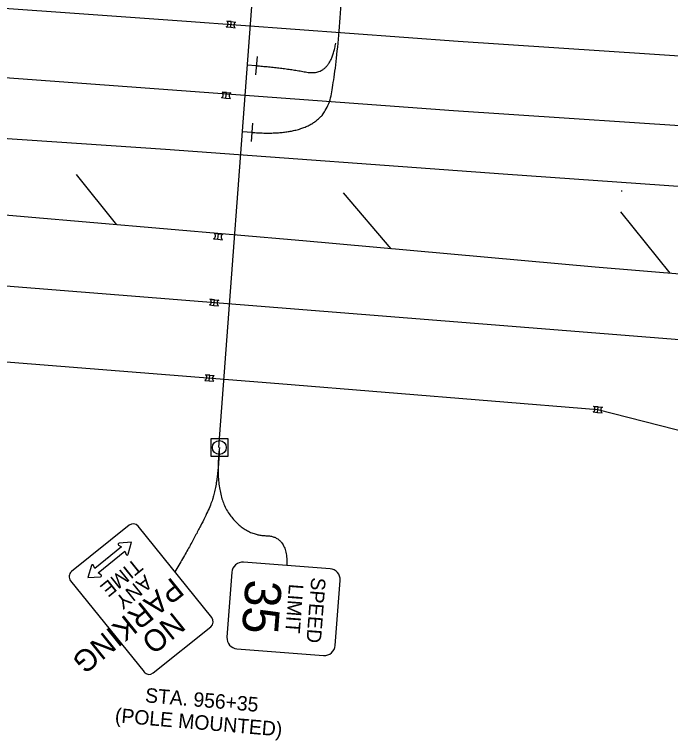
# Model space of a CAD drawing. Extents: x 1847379 to 1850904, y 217032 to 220169.
# Drawn here: x 1849731.4 to 1849844.7, y 218693.6 to 218819 of the extents above; entities that cross this region are included whole.
import ezdxf

# ---------------------------------------------------------------- set-up
doc = ezdxf.new("R2010")
doc.units = 0
for name, color, linetype in [('PM_P_Cells', 7, 'Continuous'), ('PM_P_CL_Double_Solid', 7, 'Continuous'), ('PM_P_Edge_Line', 7, 'Continuous'), ('PM_P_Lane_Line', 7, 'Continuous'), ('PM_P_Transverse_Line', 7, 'Continuous'), ('SG_X_Poles', 7, 'Continuous'), ('SN_X_Public', 7, 'Continuous'), ('SN_X_Text', 7, 'Continuous')]:
    doc.layers.add(name, color=color, linetype=linetype)

msp = doc.modelspace()

# ---------------------------------------------------------------- linework, layer by layer
at = {"layer": 'PM_P_Cells'}
for p, q in [((1849768.83, 218817.79), (1849768.06, 218817.86)), ((1849768.06, 218817.86), (1849768.83, 218817.79)), ((1849768.74, 218816.81), (1849768.83, 218817.79)), ((1849768.83, 218817.79), (1849769.59, 218817.72)), ((1849767.97, 218816.88), (1849768.74, 218816.81)), ((1849767.97, 218816.88), (1849768.74, 218816.81)), ((1849768.74, 218816.81), (1849769.51, 218816.74)), ((1849768.01, 218805.56), (1849767.24, 218805.63)), ((1849767.24, 218805.63), (1849768.01, 218805.56)), ((1849767.92, 218804.59), (1849768.01, 218805.56)), ((1849768.01, 218805.56), (1849768.78, 218805.49)), ((1849767.15, 218804.66), (1849767.92, 218804.59)), ((1849767.15, 218804.66), (1849767.92, 218804.59)), ((1849767.92, 218804.59), (1849768.69, 218804.52)), ((1849765.77, 218780.25), (1849766.54, 218780.18)), ((1849765.77, 218780.25), (1849766.54, 218780.18)), ((1849766.63, 218781.15), (1849765.86, 218781.22)), ((1849765.86, 218781.22), (1849766.63, 218781.15)), ((1849766.54, 218780.18), (1849766.63, 218781.15)), ((1849766.54, 218780.18), (1849767.31, 218780.11)), ((1849766.63, 218781.15), (1849767.4, 218781.08)), ((1849765.08, 218768.84), (1849765.84, 218768.77)), ((1849765.08, 218768.84), (1849765.84, 218768.77)), ((1849765.93, 218769.75), (1849765.16, 218769.82)), ((1849765.16, 218769.82), (1849765.93, 218769.75)), ((1849765.84, 218768.77), (1849765.93, 218769.75)), ((1849765.84, 218768.77), (1849766.61, 218768.7)), ((1849765.93, 218769.75), (1849766.7, 218769.68)), ((1849765.13, 218756.72), (1849764.36, 218756.78)), ((1849764.36, 218756.78), (1849765.13, 218756.72)), ((1849765.04, 218755.74), (1849765.13, 218756.72)), ((1849765.13, 218756.72), (1849765.9, 218756.65)), ((1849764.28, 218755.81), (1849765.04, 218755.74)), ((1849764.28, 218755.81), (1849765.04, 218755.74)), ((1849765.04, 218755.74), (1849765.81, 218755.67)), ((1849832.21, 218751.25), (1849831.44, 218751.32)), ((1849831.44, 218751.32), (1849832.21, 218751.25)), ((1849832.12, 218750.28), (1849832.21, 218751.25)), ((1849832.21, 218751.25), (1849832.98, 218751.18)), ((1849831.35, 218750.35), (1849832.12, 218750.28)), ((1849831.35, 218750.35), (1849832.12, 218750.28)), ((1849832.12, 218750.28), (1849832.89, 218750.21))]:
    msp.add_line(p, q, dxfattribs=at)
for centre, start, end in [((1849767.71, 218817.4), 296.8063, 52.8586), ((1849767.71, 218817.4), 296.8063, 52.8586), ((1849769.85, 218817.2), 116.8063, 232.8586), ((1849766.89, 218805.17), 296.8063, 52.8586), ((1849766.89, 218805.17), 296.8063, 52.8586), ((1849769.04, 218804.98), 116.8063, 232.8586), ((1849765.52, 218780.76), 296.8063, 52.8586), ((1849765.52, 218780.76), 296.8063, 52.8586), ((1849767.66, 218780.57), 116.8063, 232.8586), ((1849764.82, 218769.36), 296.8063, 52.8586), ((1849764.82, 218769.36), 296.8063, 52.8586), ((1849766.96, 218769.16), 116.8063, 232.8586), ((1849764.02, 218756.33), 296.8063, 52.8586), ((1849764.02, 218756.33), 296.8063, 52.8586), ((1849766.16, 218756.13), 116.8063, 232.8586), ((1849831.09, 218750.86), 296.8063, 52.8586), ((1849831.09, 218750.86), 296.8063, 52.8586), ((1849833.24, 218750.67), 116.8063, 232.8586)]:
    msp.add_arc(centre, 0.576, start, end, dxfattribs=at)
at = {"layer": 'PM_P_CL_Double_Solid'}
for p, q in [((1849733.07, 218784.06), (1849683.32, 218788.47)), ((1849781.21, 218779.91), (1849733.07, 218784.06)), ((1849831.69, 218775.35), (1849781.21, 218779.91)), ((1849882.04, 218771.28), (1849831.69, 218775.35))]:
    msp.add_line(p, q, dxfattribs=at)
at = {"layer": 'PM_P_Edge_Line'}
for p, q in [((1849705.27, 218799.28), (1849757.46, 218795.73)), ((1849757.46, 218795.73), (1849815.8, 218791.52)), ((1849815.8, 218791.52), (1849863.14, 218788.13))]:
    msp.add_line(p, q, dxfattribs=at)
for points in [[(1849624.07, 218766.93), (1849675.44, 218763.35), (1849725.59, 218759.36), (1849777.06, 218755.28), (1849832.17, 218750.77)], [(1849832.17, 218750.77), (1849894.17, 218734.94), (1849941.43, 218730.63), (1849992.34, 218726.14), (1850039.4, 218721.8), (1850086.44, 218717.54), (1850135.69, 218713.18), (1850171.07, 218709.94)]]:
    msp.add_lwpolyline(points, dxfattribs=at)
at = {"layer": 'PM_P_Lane_Line'}
msp.add_line((1849606.07, 218781.96), (1849881.96, 218760.04), dxfattribs=at)
for points in [[(1849608.99, 218828.81), (1849660.31, 218825.18), (1849710.18, 218821.58), (1849761.09, 218817.87), (1849808.06, 218814.41), (1849858.45, 218811.1), (1849907.69, 218807.67), (1849958.4, 218803.79), (1850015.55, 218799.15), (1850068.16, 218794.66), (1850119.07, 218790.16), (1850168.5, 218785.91), (1850217.76, 218781.65), (1850267.02, 218777.03), (1850317.3, 218772.15), (1850366.38, 218767.35), (1850416.59, 218762.59), (1850466.65, 218757.55), (1850517.86, 218752.55), (1850566.57, 218747.88), (1850616.29, 218742.91), (1850664.9, 218737.75)], [(1849608.14, 218816.84), (1849659.46, 218813.21), (1849709.31, 218809.62), (1849760.21, 218805.9), (1849807.22, 218802.44), (1849857.63, 218799.12), (1849906.82, 218795.7), (1849957.46, 218791.82), (1850014.55, 218787.19), (1850067.13, 218782.71), (1850118.03, 218778.2), (1850167.47, 218773.95), (1850186.14, 218772.34)]]:
    msp.add_lwpolyline(points, dxfattribs=at)
at = {"layer": 'PM_P_Transverse_Line'}
for p, q in [((1849742.06, 218791.39), (1849749.03, 218782.69)), ((1849788.17, 218788.23), (1849796.41, 218778.53)), ((1849836.08, 218784.95), (1849844.58, 218774.31))]:
    msp.add_line(p, q, dxfattribs=at)
at = {"layer": 'SG_X_Poles'}
msp.add_lwpolyline([(1849765.28, 218742.71), (1849768.28, 218742.71), (1849768.28, 218745.71), (1849765.28, 218745.71)], close=True, dxfattribs=at)
msp.add_circle((1849766.78, 218744.21), 1.2, dxfattribs=at)
at = {"layer": 'SN_X_Public'}
for p, q in [((1849766.69, 218744.22), (1849774.6, 218850.04)), ((1849773.28, 218811.77), (1849773.04, 218808.58)), ((1849773.16, 218810.17), (1849771.57, 218810.29)), ((1849772.51, 218800.25), (1849772.27, 218797.06)), ((1849772.39, 218798.65), (1849770.79, 218798.77)), ((1849836.25, 218788.63), (1849836.23, 218788.45)), ((1849749.38, 218727.35), (1849749.88, 218727.02)), ((1849751.62, 218727.83), (1849749.47, 218727.68)), ((1849751.03, 218725.75), (1849751.62, 218727.83)), ((1849745.84, 218722.56), (1849750.46, 218726.29)), ((1849750.46, 218726.29), (1849750.46, 218726.29)), ((1849750.46, 218726.29), (1849750.68, 218725.73)), ((1849747.66, 218725.01), (1849747.66, 218725.01)), ((1849744.68, 218723.83), (1849744.08, 218721.75)), ((1849745.24, 218723.28), (1849745.02, 218723.84)), ((1849745.83, 218722.55), (1849745.84, 218722.56)), ((1849746.33, 218722.22), (1849745.83, 218722.55)), ((1849744.08, 218721.75), (1849746.24, 218721.89))]:
    msp.add_line(p, q, dxfattribs=at)
for points in [[(1849751.17, 218730.77), (1849741.25, 218722.77)], [(1849765.46, 218714.83), (1849752.76, 218730.6)], [(1849749.88, 218727.02), (1849745.25, 218723.29)], [(1849785.91, 218723.25), (1849770.95, 218724.38)], [(1849768.94, 218722.65), (1849768.09, 218711.43)], [(1849741.08, 218721.18), (1849753.78, 218705.42)], [(1849786.79, 218710.02), (1849787.64, 218721.23)], [(1849755.37, 218705.25), (1849765.29, 218713.25)], [(1849769.82, 218709.42), (1849784.78, 218708.29)]]:
    msp.add_lwpolyline(points, dxfattribs=at)
for centre, radius, start, end in [((1849751.88, 218729.89), 1.12, 38.8676, 128.8676), ((1849749.48, 218727.5), 0.182, 93.7884, 236.5054), ((1849750.85, 218725.8), 0.182, 201.2298, 343.9469), ((1849744.85, 218723.78), 0.182, 21.2298, 163.9469), ((1849770.81, 218722.51), 1.88, 85.6628, 175.6628), ((1849741.95, 218721.89), 1.12, 128.8676, 218.8676), ((1849785.77, 218721.38), 1.88, 355.6628, 85.6628), ((1849746.23, 218722.07), 0.182, 273.7884, 56.5054), ((1849764.59, 218714.12), 1.12, 308.8676, 38.8676), ((1849769.96, 218711.29), 1.87, 175.6628, 265.6628), ((1849784.92, 218710.16), 1.88, 265.6628, 355.6628), ((1849754.66, 218706.12), 1.12, 218.8676, 308.8676)]:
    msp.add_arc(centre, radius, start, end, dxfattribs=at)
at = {"layer": 'SN_X_Text'}
for points in [[(1849772.39, 218798.65), (1849784.27, 218797.71), (1849787.59, 218811.21), (1849789.54, 218860.25), (1849786.3, 218904.05), (1849800.32, 218903.43)], [(1849773.16, 218810.17), (1849777.63, 218809.86), (1849785.98, 218808.28), (1849786.88, 218814.06)], [(1849766.78, 218744.21), (1849766.6, 218738.74), (1849764.81, 218732.47), (1849759.11, 218722.71)], [(1849766.78, 218744.21), (1849765.89, 218736.28), (1849771.19, 218729.03), (1849778.6, 218728.9), (1849778.43, 218723.81)]]:
    msp.add_open_spline(points, degree=2, dxfattribs=at)

# ---------------------------------------------------------------- texts
at = {"layer": 'SN_X_Public'}
for s, height, rotation, p in [('TIME', 2.5, 218.8676, (1849752.21, 218725.18)), ('ANY', 2.5, 218.8676, (1849753.91, 218722.34)), ('PARKING', 3.75, 218.8676, (1849758.63, 218721.93)), ('35', 6.25, 265.6628, (1849771.36, 218721.52)), ('SPEED', 2.5, 265.6628, (1849782.67, 218721.82)), ('LIMIT', 2.5, 265.6628, (1849778.82, 218720.7)), ('NO', 3.75, 218.8676, (1849758.88, 218715.91))]:
    msp.add_text(s, height=height, rotation=rotation, dxfattribs=at).set_placement(p)
at = {"layer": 'SN_X_Text'}
for s, p in [('STA. 956+35', (1849753.88, 218700.19)), ('(POLE MOUNTED)', (1849748.67, 218696.72))]:
    msp.add_text(s, height=2.5, rotation=355.1482, dxfattribs=at).set_placement(p)

doc.saveas('drawing.dxf')
